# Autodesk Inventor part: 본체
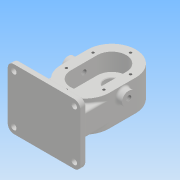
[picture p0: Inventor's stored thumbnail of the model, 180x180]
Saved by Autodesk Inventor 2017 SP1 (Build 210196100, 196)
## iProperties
Part Number: 본체
Material: 일반
Document SubType Name: Modeling
Designer: 00-00
Density: 1 g/cm^3
Appearance: 기본값
Author: 00-00
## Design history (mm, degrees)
sketch "스케치1"
  geometry: L1 (-40, 124)-(40, 124); L2 (40, 124)-(40, 0); L3 (40, 0)-(-40, 0); L4 (-40, 0)-(-40, 124); A1 r 40 centre (0, 84) between (40, 84) and (-40, 84); A2 r 40 centre (0, 40) between (-40, 40) and (40, 40); 2 further points
  constraints: 8 end point, 4 point on circle, 4 point on line, 2 centre point, 2 parallel, 2 tangent, 2 vertical alignment, 1 coincident, 1 horizontal, 1 midpoint, 1 perpendicular
  dimensions: "d9" = 80 distance of L2.end L3.end; "d10" = 124 distance of L1.end L2.end; "d11" = 40 radius of A1; "d12" = 40 radius of A2
extrude "돌출1" new body sketch "스케치1" stored distance "d13" = 53; taper "d14" = 0 deg
sketch "스케치2"
  geometry: L1 (0, 84)-(0, 40); L2 (-24, 84)-(-24, 40); L3 (24, 40)-(24, 84); A1 r 24 centre (0, 84) between (24, 84) and (-24, 84); A2 r 24 centre (0, 40) between (-24, 40) and (24, 40); A3 r 40 centre (0, 40) between (-40, 40) and (40, 40) reference; A4 r 40 centre (0, 84) between (40, 84) and (-40, 84) reference; 4 further points
  constraints: 8 end point, 6 point on circle, 4 tangent, 3 vertical alignment, 2 centre point, 1 concentric, 1 midpoint, 1 parallel
  dimensions: "d15" = 24 radius of A1; "d16" = 44 distance of L3.start L3.end
extrude "돌출2" cut sketch "스케치2" distance "d17" = 29; taper "d18" = 0 deg
sketch "스케치3"
  geometry: L1 (24, 40)-(24, 84) reference; L2 (-24, 84)-(-24, 40) reference; C1 r 19 at (0, 84); A1 r 24 centre (0, 40) between (-24, 40) and (24, 40) reference; A2 r 24 centre (0, 84) between (24, 84) and (-24, 84) reference; 1 further point
  constraints: 1 centre point, 1 coincident
  dimensions: "d19" = 19 radius of C1
extrude "돌출3" join sketch "스케치3" distance "d20" = 17; taper "d21" = 0 deg
sketch "스케치5"
  geometry: C1 r 12.5 at (0, 84); C2 r 12.5 at (0, 40); A1 r 24 centre (0, 84) between (24, 84) and (-24, 84) reference; A2 r 24 centre (0, 40) between (-24, 40) and (24, 40) reference; 1 further point
  constraints: 2 centre point, 2 coincident
  dimensions: "d22" = 12.5 radius of C1; "d23" = 12.5 radius of C2
extrude "돌출4" cut sketch "스케치5" distance "d24" = 15; taper "d25" = 0 deg
sketch "스케치6"
  geometry: C1 r 19 at (0, 0) reference; C2 r 8.5 at (0, 0); 1 further point
  constraints: 1 centre point, 1 coincident
  dimensions: "d26" = 8.5 radius of C2
extrude "돌출5" cut sketch "스케치6" stored distance "d27" = 15; taper "d28" = 0 deg
sketch "스케치7"
  geometry: L1 (-24, 40)-(-24, 84) reference; L2 (24, 84)-(24, 40) reference; L3 (0, 84)-(0, 40); L4 (-31, 84)-(-31, 40); L5 (31, 40)-(31, 84); C1 r 12.5 at (0, 84) reference; C2 r 12.5 at (0, 40) reference; A1 r 24 centre (0, 84) between (24, 84) and (-24, 84) reference; A2 r 24 centre (0, 40) between (-24, 40) and (24, 40) reference; A3 r 24 centre (0, 84) between (24, 84) and (-24, 84) reference; A4 r 31 centre (0, 84) between (31, 84) and (-31, 84); A5 r 31 centre (0, 40) between (-31, 40) and (31, 40); 7 further points
  constraints: 8 end point, 5 point on circle, 4 coincident, 4 tangent, 2 centre point, 1 midpoint, 1 parallel, 1 vertical
  dimensions: "d29" = 31 radius of A4
  node "투영된 루프3"
hole "구멍1" sketch "스케치7" diameter "d30" = 4.134; stored, may be unused: countersink angle "d34" = 90 deg, drill point angle "d36" = 118 deg; dims "d31" = 10, "d32" = 4, "d33" = 2, "d35" = 12
sketch "스케치8"
  geometry: C1 r 8.5 at (0, 0) reference; C2 r 19 at (0, 0) reference; C3 r 14 at (0, 0); 1 further point
  constraints: 1 centre point, 1 coincident
  dimensions: "d37" = 14 radius of C3
extrude "돌출6" cut sketch "스케치8" distance "d38" = 7.3; taper "d39" = 0 deg
chamfer "모따기1" distance "d40" = 0.7; stored, may be unused: second distance "d41" = 2, angle "d42" = 30 deg
fillet "모깎기1" dims "d43" = 0.5
chamfer "모따기2" distance "d44" = 1; stored, may be unused: second distance "d45" = 2, angle "d46" = 30 deg
node "작업 평면1"
node "작업 평면2"
sketch "스케치9"
  geometry: L1 (40, 26.5)-(-40, 26.5) reference; L2 (40, -26.5)-(40, 26.5) reference; L3 (-40, 26.5)-(40, 26.5) reference; L4 (-40, -26.5)-(-40, 26.5) reference; L5 (40, -26.5)-(-40, -26.5) reference; L6 (40, -26.5)-(40, 26.5) reference; L7 (-19, -43.5)-(19, -43.5) reference; L8 (60, 56.5)-(-60, 56.5); L9 (-60, 56.5)-(-60, -43.5); L10 (-60, -43.5)-(60, -43.5); L11 (60, -43.5)-(60, 56.5); 2 further points
  constraints: 8 end point, 2 midpoint, 2 parallel, 1 horizontal, 1 perpendicular
  dimensions: "d48" = 120 distance of L10.end L9.end; "d49" = 100 distance of L9.end L8.end
extrude "돌출7" join sketch "스케치9" distance "d50" = 10; taper "d51" = 0 deg
sketch "스케치10"
  geometry: L1 (-40, -18.5)-(40, -18.5); L2 (40, -18.5)-(40, 18.5); L3 (40, 18.5)-(-40, 18.5); L4 (-40, 18.5)-(-40, -18.5); L5 (60, 43.5)-(-60, 43.5) reference; 2 further points
  constraints: 8 end point, 2 parallel, 1 horizontal, 1 midpoint, 1 perpendicular, 1 vertical alignment
  dimensions: "d52" = 80 distance of L3.end L2.end; "d53" = 37 distance of L2.end L1.end; "d54" = 25 distance between parallel lines of L5 L3
extrude "돌출8" join sketch "스케치10" stored distance "d55" = 10; taper "d56" = 0 deg
sketch "스케치11"
  geometry: L1 (53, 84)-(0, 84) reference; L2 (53, -40)-(45, -40) reference; L3 (0, 84)-(0, 44) reference; L4 (53, 44)-(53, 84) reference; L5 (44, 31.5)-(44, 56.5) reference; L6 (53, 44)-(0, 44) reference; L7 (0, 44)-(0, 44) reference; L8 (53, 44)-(0, 44) reference; L9 (53, 44)-(53, 44) reference; L10 (0, 44)-(0, 0) reference; C1 r 11 at (14, 22); 1 further point
  constraints: 1 centre point
  dimensions: "d57" = 11 radius of C1; "d58" = 14 distance from line of C1.centre L10; "d59" = 22 distance from line of C1.centre L6
extrude "돌출9" join sketch "스케치11" distance "d60" = 10; taper "d61" = 0 deg
sketch "스케치13"
  geometry: C1 r 11 at (0, 0) reference; 2 further points
  constraints: 1 coincident
hole "구멍2" sketch "스케치13" at (0, 0) diameter "d62" = 8.376; stored, may be unused: countersink angle "d66" = 90 deg, drill point angle "d68" = 0 deg; dims "d63" = 20, "d64" = 4, "d65" = 2, "d67" = 27.3
sketch "스케치14"
  geometry: L1 (-60, 43.5)-(-60, -56.5) reference; L2 (-60, -56.5)-(60, -56.5) reference; 2 further points
  constraints: 1 other
  dimensions: "d69" = 60 distance from line of point (0, -44.5) L1; "d70" = 12 distance from line of point (0, -44.5) L2
feature "엠보싱1" sketch "스케치14" dims "d9" = 80, "d10" = 124, "d11" = 40, "d12" = 40, "d15" = 24, "d16" = 44, "d71" = 0.5, "d72" = 0
fillet "모깎기2" dims "d73" = 10
sketch "스케치15"
  geometry: L1 (-60, 33.5)-(-60, -46.5) reference; L2 (50, 43.5)-(-50, 43.5) reference; L3 (60, -46.5)-(60, 33.5) reference; L4 (-50, -56.5)-(50, -56.5) reference; A1 r 10 centre (-50, -46.5) between (-60, -46.5) and (-50, -56.5) reference; A2 r 10 centre (-50, 33.5) between (-50, 43.5) and (-60, 33.5) reference; A3 r 10 centre (50, 33.5) between (60, 33.5) and (50, 43.5) reference; A4 r 10 centre (50, -46.5) between (50, -56.5) and (60, -46.5) reference; 5 further points
  constraints: 4 coincident
hole "구멍3" sketch "스케치15" at (-50, 33.5), (50, 33.5), (50, -46.5), (-50, -46.5) diameter "d74" = 9; stored, may be unused: countersink angle "d78" = 90 deg, drill point angle "d80" = 0 deg; dims "d75" = 20, "d76" = 4, "d77" = 2, "d79" = 27.3
fillet "모깎기3" dims "d81" = 3
fillet "모깎기4" dims "d82" = 3
fillet "모깎기5" dims "d83" = 3
fillet "모깎기6" dims "d84" = 3
sketch "스케치16"
  geometry: L1 (-24, 40)-(-24, 84) reference; L2 (24, 84)-(24, 40) reference; L3 (40, 40)-(40, 62) reference; L4 (40, 62)-(40, 84) reference; L5 (-40, 84)-(-40, 62) reference; L6 (-40, 62)-(-40, 40) reference; C1 r 2.067 at (31, 40) reference; C2 r 2.067 at (-31, 84) reference; C3 r 2.067 at (0, 115) reference; C4 r 2.067 at (-31, 40) reference; C5 r 2.067 at (31, 84) reference; A1 r 24 centre (0, 40) between (-24, 40) and (24, 40) reference; A2 r 24 centre (0, 84) between (24, 84) and (-24, 84) reference; A3 r 40 centre (0, 40) between (-40, 40) and (40, 40) reference; A4 r 40 centre (0, 84) between (40, 84) and (-40, 84) reference; 2 further points
  constraints: 1 vertical alignment
  dimensions: "d86" = 106 distance of C3.centre point (0, 9)
hole "구멍4" sketch "스케치16" at (0, 9) diameter "d87" = 4.134; stored, may be unused: countersink angle "d91" = 90 deg, drill point angle "d93" = 118 deg; dims "d88" = 10, "d89" = 4, "d90" = 2, "d92" = 12
fillet "모깎기7" dims "d94" = 3
node "솔리드1"
mirror "미러1"
node "투영된 루프1"
node "투영된 루프2"
node "투영된 루프4"
node "투영된 루프5"
node "투영된 루프6"
node "투영된 루프8"
node "투영된 루프9"
other parameters: "d47" = -28
